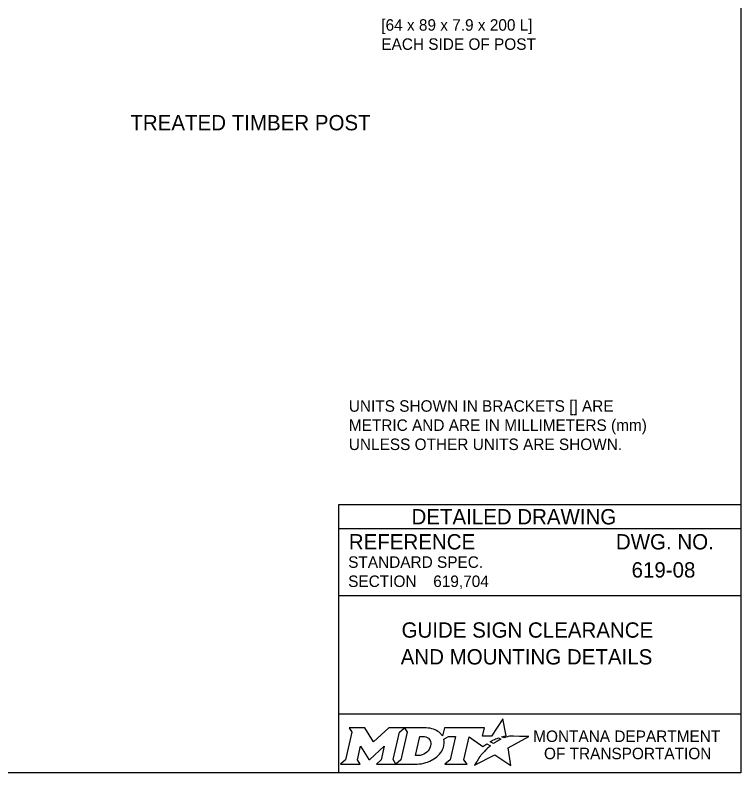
# Model space of a CAD drawing. Extents: x 49991.4 to 50021, y 49987.6 to 50011.4.
# Drawn here: x 50012.962 to 50016.75, y 49987.799 to 49991.756 of the extents above; entities that cross this region are included whole.
import ezdxf

# ---------------------------------------------------------------- set-up
doc = ezdxf.new("R2010")
doc.units = 0
for name, color, linetype in [('Default', 7, 'Continuous'), ('Level 1', 7, 'Continuous'), ('Level 2', 7, 'Continuous'), ('Level 5', 7, 'Continuous')]:
    doc.layers.add(name, color=color, linetype=linetype)

msp = doc.modelspace()

# ---------------------------------------------------------------- linework, layer by layer
at = {"layer": 'Default'}
for points in [[(50015.5126, 49987.9811), (50015.5023, 49987.9867), (50015.5139, 49987.9895), (50015.5255, 49987.9915), (50015.5081, 49988.0816), (50015.4486, 49987.9903), (50015.4013, 49987.9896), (50015.4116, 49988.0337), (50015.2024, 49988.0338), (50015.1923, 49987.9913), (50015.1865, 49987.9996)], [(50014.7056, 49988.0338), (50014.7197, 49988.0104), (50014.6862, 49987.8671), (50014.6605, 49987.8446), (50014.7621, 49987.8446), (50014.7486, 49987.8674), (50014.7648, 49987.9375), (50014.8085, 49987.8685), (50014.8138, 49987.8685), (50014.8889, 49987.938), (50014.8725, 49987.8669), (50014.8478, 49987.8449), (50014.9494, 49987.8449), (50014.9356, 49987.8682), (50014.9688, 49988.0106)], [(50014.9688, 49988.0106), (50014.9941, 49988.0338), (50014.9117, 49988.0338), (50014.8321, 49987.9608), (50014.7876, 49988.0335), (50014.7056, 49988.0338)], [(50015.1077, 49988.0338), (50014.9941, 49988.0338), (50015.0088, 49988.0109), (50014.9749, 49987.8671), (50014.9494, 49987.8449), (50015.06, 49987.8449)], [(50015.1317, 49987.9471), (50015.1305, 49987.939), (50015.1273, 49987.9297), (50015.1231, 49987.9215), (50015.1175, 49987.914), (50015.111, 49987.9071), (50015.1031, 49987.9008), (50015.0948, 49987.8961), (50015.0857, 49987.8922), (50015.0766, 49987.8899), (50015.0674, 49987.889), (50015.0515, 49987.889), (50015.0751, 49987.989), (50015.0911, 49987.989), (50015.0987, 49987.9884), (50015.1063, 49987.9865), (50015.1129, 49987.9835), (50015.119, 49987.9793), (50015.1238, 49987.9743), (50015.1275, 49987.9683), (50015.1302, 49987.9621), (50015.1318, 49987.9547), (50015.1318, 49987.9517), (50015.1317, 49987.9471)], [(50015.1991, 49987.9747), (50015.2237, 49987.9878), (50015.2606, 49987.9878), (50015.232, 49987.8673), (50015.2045, 49987.8446), (50015.3207, 49987.8446), (50015.3037, 49987.8675), (50015.3319, 49987.9877), (50015.4032, 49987.936), (50015.4243, 49987.9511), (50015.444, 49987.9402)], [(50015.3882, 49987.8843), (50015.3729, 49987.8599), (50015.3682, 49987.8524), (50015.3624, 49987.8438), (50015.3601, 49987.8395), (50015.4654, 49987.8926), (50015.5493, 49987.8375), (50015.5362, 49987.9302), (50015.6431, 49987.9886), (50015.5938, 49987.9894), (50015.5637, 49987.9898), (50015.5429, 49987.9901), (50015.5361, 49987.9886), (50015.5312, 49987.9874), (50015.5228, 49987.9851), (50015.5126, 49987.9811)], [(50015.4622, 49987.9535), (50015.4598, 49987.9518), (50015.4415, 49987.9614), (50015.4518, 49987.9671), (50015.4559, 49987.9693), (50015.4645, 49987.9733), (50015.4702, 49987.9759), (50015.4781, 49987.9789), (50015.4854, 49987.9816), (50015.4972, 49987.9742), (50015.4932, 49987.9721), (50015.4886, 49987.9696), (50015.4844, 49987.9674), (50015.4794, 49987.9645), (50015.4775, 49987.9634), (50015.4748, 49987.9618), (50015.4723, 49987.9604), (50015.47, 49987.9588), (50015.4674, 49987.957), (50015.4647, 49987.9552), (50015.4622, 49987.9535)], [(50015.4021, 49987.9004), (50015.4021, 49987.9004)], [(50015.1057, 49987.8522), (50015.1141, 49987.8548), (50015.1271, 49987.8602), (50015.1475, 49987.8712)]]:
    msp.add_lwpolyline(points, dxfattribs=at)
for centre, radius, start, end in [((50015.1308, 49987.9554), 0.0709, 339.5329, 15.8582), ((50015.0868, 49987.9727), 0.1183, 300.9103, 339.1383)]:
    msp.add_arc(centre, radius, start, end, dxfattribs=at)
for centre, major_axis, ratio, start_param, end_param in [((50015.1056, 49987.9864), (0.0834, -0.0037), 0.568097, 0.61298, 1.570796), ((50015.1612, 49987.9937), (0.0361, -0.0295), 0.469099, 1.225588, 1.570796), ((50015.4119, 49987.9106), (-0.0098, -0.0102), 0.016458, 3.141593, 6.279097), ((50015.4329, 49987.9305), (-0.0112, -0.0097), 0.021651, 3.157348, 6.283185), ((50015.3952, 49987.8923), (-0.00694, -0.00806), 0.008222, 0, 3.137361), ((50015.0603, 49987.9932), (0, 0.1484), 0.987302, 3.139398, 3.456847)]:
    msp.add_ellipse(centre, major_axis=major_axis, ratio=ratio, start_param=start_param, end_param=end_param, dxfattribs=at)
at = {"layer": 'Level 1'}
msp.add_lwpolyline([(49999.3835, 49998.9992), (50016.7501, 49998.9992), (50016.7501, 49987.7988), (49999.3835, 49987.7988)], close=True, dxfattribs=at)
at = {"layer": 'Level 5'}
for p, q in [((50016.7501, 49989.1988), (50014.6501, 49989.1988)), ((50014.6501, 49989.1988), (50014.6501, 49987.7988)), ((50016.7501, 49989.0738), (50014.6501, 49989.0738)), ((50016.3862, 49988.8587), (50016.3862, 49988.8587)), ((50015.1444, 49988.7993), (50015.1444, 49988.7993)), ((50016.7501, 49988.7238), (50014.6501, 49988.7238)), ((50015.7001, 49988.4747), (50015.7001, 49988.4747)), ((50016.7501, 49988.1057), (50014.6501, 49988.1057))]:
    msp.add_line(p, q, dxfattribs=at)

# ---------------------------------------------------------------- texts
at = {"layer": 'Default'}
for s, p in [('MONTANA DEPARTMENT', (50015.6663, 49987.96)), ('OF TRANSPORTATION', (50015.7225, 49987.87))]:
    msp.add_text(s, height=0.06, dxfattribs=at).set_placement(p)
at = {"layer": 'Level 2'}
for s, height, p in [('[64 x 89 x 7.9 x 200 L]', 0.06, (50014.8733, 49991.6745)), ('EACH SIDE OF POST', 0.06, (50014.8733, 49991.5745)), ('TREATED TIMBER POST', 0.08, (50013.5634, 49991.1542)), ('UNITS SHOWN IN BRACKETS [] ARE ', 0.06, (50014.7038, 49989.6846)), ('METRIC AND ARE IN MILLIMETERS (mm) ', 0.06, (50014.7038, 49989.5846)), ('UNLESS OTHER UNITS ARE SHOWN.', 0.06, (50014.7038, 49989.4846)), ('619-08', 0.08, (50016.1798, 49988.8187)), ('619,704', 0.06, (50015.1444, 49988.7693)), ('GUIDE SIGN CLEARANCE', 0.08, (50014.9791, 49988.5047)), ('AND MOUNTING DETAILS', 0.08, (50014.9745, 49988.3647))]:
    msp.add_text(s, height=height, dxfattribs=at).set_placement(p)
at = {"layer": 'Level 5'}
for s, height, p in [('DETAILED DRAWING', 0.0799, (50015.0311, 49989.0963)), ('REFERENCE', 0.08, (50014.7037, 49988.9654)), ('DWG. NO.', 0.08, (50016.0979, 49988.9654)), ('STANDARD SPEC.', 0.06, (50014.7004, 49988.8694)), ('SECTION', 0.06, (50014.7004, 49988.7694))]:
    msp.add_text(s, height=height, dxfattribs=at).set_placement(p)

doc.saveas('drawing.dxf')
